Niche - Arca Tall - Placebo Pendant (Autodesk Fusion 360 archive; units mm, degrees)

design "Arca - Tall - Modular" references "Modular - Placedo - Cord Set", "Modular - Placebo - Bayonet Connector"
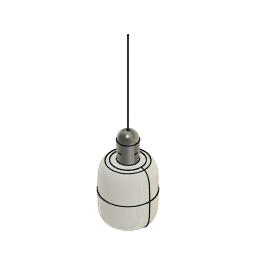
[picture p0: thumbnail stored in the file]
sketch "Sketch1" plane through (0, 0, 0) normal (0, 1, 0) x axis (1, 0, 0)
  line L1 (127, 0) -> (-127, 0)
  line L2 (0, 127) -> (0, -132.08)
  line L3 (26.9875, 127) -> (26.9875, -132.08)
  line L4 (-26.9875, 127) -> (-26.9875, -132.08)
  line L5 (127, -114.3) -> (-127, -114.3)
  line L6 (127, 114.3) -> (-127, 114.3)
  line L7 (95.25, 127) -> (95.25, -127)
  line L8 (-95.25, 127) -> (-95.25, -127)
  line L9 (127, -119.38) -> (-127, -119.38)
  line L10 (127, -132.08) -> (-127, -132.08)
  point P5 (26.9875, 127)
  point P6 (-26.9875, 127)
  point P7 (-127, -114.3)
  point P9 (-127, 114.3)
  point P8 (127, -114.3)
  point P10 (127, 114.3)
  point P12 (95.25, 127)
  point P14 (-95.25, 127)
  point P19 (-26.9875, -132.08)
  point P20 (0, -132.08)
  point P21 (26.9875, -132.08)
  horizontal L1
  vertical L2
  symmetric L2 P5 P6
  symmetric L1 P7 P9
  symmetric L1 P8 P10
  symmetric L2 P12 P14
  coincident L10 P19
  coincident L10 P20
  coincident L10 P21
  dimension "d2" = 114.3
  dimension "d3" = 95.25
  dimension "d4" = 119.38
  dimension "d5" = 132.08
derived_base_feature "Derived Base Feature"
sketch "Sketch2" plane through (0, 0, 0) normal (0, 1, 0) x axis (1, 0, 0)
  curve K1 (71.6837, -115.2107) -> (95.6809, -6.8986)
  curve K2 (52.8501, 110.047) -> (95.6809, -6.8478)
  line L1 (6.35, 114.3) -> (14.1394, 114.3)
  line L2 (0, 114.3) -> (6.35, 114.3)
  line L3 (95.6809, -6.8986) -> (95.6809, -6.8732)
  line L4 (95.6809, -6.8478) -> (95.6809, -6.8732)
  line L5 (0, 114.3) -> (0, -152.4)
  line L6 (26.9875, 114.3) -> (26.9875, -152.4)
  line L7 (127, 0) -> (-127, 0)
  line L8 (26.9875, -152.4) -> (26.9875, -124.1529)
  curve K3 (71.6837, -115.2107) -> (57.3444, -118.8227)
  curve K4 (97.0837, -115.2107) -> (121.0809, -6.8986)
  line L9 (-5.08, -132.08) -> (30.48, -132.08)
  curve K5 (95.6814, 4.9187) -> (95.6809, -6.8478)
  curve K6 (95.1681, 22.0412) -> (95.6814, 4.9187)
  curve K7 (94.696, 36.0588) -> (95.1681, 22.0412)
  curve K8 (94.3798, 46.8578) -> (94.696, 36.0588)
  curve K9 (93.5014, 59.02) -> (94.3798, 46.8578)
  curve K10 (92.6826, 66.7361) -> (93.5014, 59.02)
  curve K11 (87.4432, 83.6792) -> (92.6826, 66.7361)
  curve K12 (83.6663, 89.9171) -> (87.4432, 83.6792)
  curve K13 (81.2455, 93.6814) -> (83.6663, 89.9171)
  curve K14 (79.8608, 95.2739) -> (81.2455, 93.6814)
  curve K15 (76.5846, 98.3024) -> (79.8608, 95.2739)
  curve K16 (71.12, 103.378) -> (76.5846, 98.3024)
  curve K17 (62.23, 107.188) -> (71.12, 103.378)
  curve K18 (60.3553, 107.865) -> (62.23, 107.188)
  curve K19 (55.4987, 109.407) -> (60.3553, 107.865)
  curve K20 (54.6982, 109.6954) -> (55.4987, 109.407)
  curve K21 (52.8501, 110.047) -> (54.6982, 109.6954)
  curve K22 (95.6814, -18.6651) -> (95.6809, -6.8986)
  curve K23 (95.1681, -35.7876) -> (95.6814, -18.6651)
  curve K24 (94.696, -49.8052) -> (95.1681, -35.7876)
  curve K25 (94.3798, -60.6043) -> (94.696, -49.8052)
  curve K26 (93.5014, -72.7665) -> (94.3798, -60.6043)
  curve K27 (92.6826, -80.4825) -> (93.5014, -72.7665)
  curve K28 (87.4432, -97.4257) -> (92.6826, -80.4825)
  curve K29 (83.6663, -103.6635) -> (87.4432, -97.4257)
  curve K30 (81.2455, -107.4278) -> (83.6663, -103.6635)
  curve K31 (79.8608, -109.0204) -> (81.2455, -107.4278)
  curve K32 (77.083, -111.5881) -> (79.8608, -109.0204)
  curve K33 (75.5537, -112.9298) -> (77.083, -111.5881)
  curve K34 (71.6837, -115.2107) -> (75.5537, -112.9298)
  arc A1 centre (13.3279, -71.3849) radius 185.6867 clockwise from (14.1394, 114.3) to (52.8501, 110.047)
  arc A2 centre (29.1167, 64.7059) radius 185.6867 clockwise from (57.3444, -118.8227) to (30.1449, -120.978)
  arc A3 centre (30.1625, -124.1529) radius 3.175 clockwise from (26.9875, -124.1529) to (30.1449, -120.978)
  point P9 (0, 114.3)
  point P13 (0, 114.3)
  coincident P9 P13
  perpendicular L2 L5
  tangent A2 A3
  tangent L8 A3
  perpendicular L5 L9
  dimension "d6" = 26.9875
  dimension "d8" radius A3 = 3.175
revolve "Revolve1" sketch "Sketch2" AlongAngle 360 bodies "Arca Tall - Modular"
shell "Shell1" innerThickness 1.27
component_from_bodies "Body->Comp1"
component_insert "Component Insert1"
component_insert "Component Insert2"
sketch "Sketch3" plane through (0, 0, 0) normal (0, 1, 0) x axis (1, 0, 0)
  curve K1 (58.1849, -116.188) -> (46.5459, -119.1199)
  curve K2 (47.1736, -119.0144) -> (46.5459, -119.1199)
  curve K3 (49.4816, -118.6521) -> (47.1736, -119.0144)
  curve K4 (51.9142, -118.2661) -> (49.4816, -118.6521)
  curve K5 (54.2138, -117.7227) -> (51.9142, -118.2661)
  curve K6 (56.724, -116.9155) -> (54.2138, -117.7227)
  curve K7 (58.1849, -116.188) -> (56.724, -116.9155)
  curve K8 (58.1849, -116.188) -> (77.6633, -28.2722)
  curve K9 (77.6636, -37.823) -> (77.6633, -28.2722)
  curve K10 (77.247, -51.7211) -> (77.6636, -37.823)
  curve K11 (76.8638, -63.0991) -> (77.247, -51.7211)
  curve K12 (76.6071, -71.8645) -> (76.8638, -63.0991)
  curve K13 (75.8941, -81.7365) -> (76.6071, -71.8645)
  curve K14 (75.2295, -87.9995) -> (75.8941, -81.7365)
  curve K15 (70.9767, -101.7521) -> (75.2295, -87.9995)
  curve K16 (67.9111, -106.8153) -> (70.9767, -101.7521)
  curve K17 (65.9461, -109.8707) -> (67.9111, -106.8153)
  curve K18 (64.8222, -111.1634) -> (65.9461, -109.8707)
  curve K19 (62.5675, -113.2476) -> (64.8222, -111.1634)
  curve K20 (61.3262, -114.3366) -> (62.5675, -113.2476)
  curve K21 (58.1849, -116.188) -> (61.3262, -114.3366)
  curve K22 (42.8979, 66.6514) -> (77.6633, -28.2309)
  curve K23 (77.6636, -18.6802) -> (77.6633, -28.2309)
  curve K24 (77.247, -4.782) -> (77.6636, -18.6802)
  curve K25 (76.8638, 6.5959) -> (77.247, -4.782)
  curve K26 (76.6071, 15.3614) -> (76.8638, 6.5959)
  curve K27 (75.8941, 25.2333) -> (76.6071, 15.3614)
  curve K28 (75.2295, 31.4964) -> (75.8941, 25.2333)
  curve K29 (70.9767, 45.249) -> (75.2295, 31.4964)
  curve K30 (67.9111, 50.3122) -> (70.9767, 45.249)
  curve K31 (65.9461, 53.3676) -> (67.9111, 50.3122)
  curve K32 (64.8222, 54.6603) -> (65.9461, 53.3676)
  curve K33 (62.163, 57.1184) -> (64.8222, 54.6603)
  curve K34 (57.7274, 61.2383) -> (62.163, 57.1184)
  curve K35 (50.5115, 64.3308) -> (57.7274, 61.2383)
  curve K36 (48.9898, 64.8803) -> (50.5115, 64.3308)
  curve K37 (45.0478, 66.1319) -> (48.9898, 64.8803)
  curve K38 (44.398, 66.366) -> (45.0478, 66.1319)
  curve K39 (42.8979, 66.6514) -> (44.398, 66.366)
  line L1 (77.6633, -28.2722) -> (77.6633, -28.2516)
  line L2 (77.6633, -28.2309) -> (77.6633, -28.2516)
  line L3 (5.1542, 70.1035) -> (11.4768, 70.1035)
  line L4 (0, 70.1035) -> (5.1542, 70.1035)
  line L5 (0, -120.4006) -> (0, 70.1035)
  line L6 (0, 70.0994) -> (0, -120.4006)
  line L7 (0, -133.1006) -> (26.924, -133.1006)
  line L8 (0, -120.4006) -> (0, -133.1006)
  line L9 (26.924, -120.8356) -> (26.924, -133.1006)
  line L10 (26.924, 70.0994) -> (26.924, 69.242)
  arc A1 centre (23.6338, 29.8485) radius 150.72 clockwise from (46.5459, -119.1199) to (26.924, -120.8356)
  arc A2 centre (10.8181, -80.6151) radius 150.72 clockwise from (11.4768, 70.1035) to (42.8979, 66.6514)
  point P52 (26.924, 69.242)
  point P46 (0, -120.4006)
  point P47 (0, 70.0994)
  point P48 (26.924, -133.1006)
  point P49 (26.924, 70.0994)
  perpendicular L7 L9
  perpendicular L7 L8
  coincident A2 P52
  collinear L9 L10
  dimension "d11" distance P46 P47 = 190.5
  dimension "d13" distance P48 P49 = 203.2
revolve "Revolve2" sketch "Sketch3" AlongAngle 360 bodies "Arca Tall V2 - Modular"
shell "Shell2" innerThickness 1.27
component_from_bodies "Body->Comp2"
position "Position1"
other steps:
base_feature "Base Feature1" bodies "Arca Tall V2 - Modular"
base_feature "Base Feature1" bodies "Arca Tall - Modular"
create_component "CreateComponent1"
remove_body "RemoveBody1"
create_component "CreateComponent2"
remove_body "RemoveBody2"
named bodies: "Arca Tall - Modular", "Arca Tall V2 - Modular"

design "Modular - Placebo - Bayonet Connector"
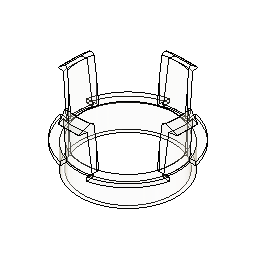
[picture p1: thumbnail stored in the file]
sketch "Sketch1" plane through (0, 0, 0) normal (0, 0, 1) x axis (1, 0, 0)
  circle C1 centre (0, 0) radius 23.241
  point P1 (0, 0)
  point P2 (0, 0)
  coincident P1 P2
  dimension "d1" diameter C1 = 46.482
extrude "Extrude1" new body sketch "Sketch1" along normal blind 11.176
sketch "Sketch2" plane through (0, 0, 11.176) normal (0, 0, 1) x axis (-1, 0, 0)
  line L1 (-23.2795, -6.35) -> (-26.1645, -6.35)
  line L2 (-23.2795, 6.35) -> (-26.1645, 6.35)
  line L3 (26.1645, -6.35) -> (23.2795, -6.35)
  line L4 (26.1645, 6.35) -> (23.2795, 6.35)
  line L5 (6.35, -23.2795) -> (6.35, -26.1645)
  line L6 (-6.35, -23.2795) -> (-6.35, -26.1645)
  line L7 (6.35, 26.1645) -> (6.35, 23.2795)
  line L8 (-6.35, 26.1645) -> (-6.35, 23.2795)
  line L9 (0, -24.13) -> (0, -26.924)
  line L10 (6.35, -23.2795) -> (6.35, -22.3567)
  line L11 (-6.35, -23.2795) -> (-6.35, -22.3567)
  line L12 (23.2795, -6.35) -> (22.3567, -6.35)
  line L13 (23.2795, 6.35) -> (22.3567, 6.35)
  line L14 (-23.2795, 6.35) -> (-22.3567, 6.35)
  line L15 (-23.2795, -6.35) -> (-22.3567, -6.35)
  line L16 (6.35, 22.3567) -> (6.35, 23.2795)
  line L17 (-6.35, 22.3567) -> (-6.35, 23.2795)
  circle C1 centre (0, 0) radius 23.241
  arc A1 centre (0, 0) radius 26.924 clockwise from (-6.35, -26.1645) to (-26.1645, -6.35)
  arc A2 centre (0, 0) radius 26.924 clockwise from (26.1645, -6.35) to (6.35, -26.1645)
  arc A3 centre (0, 0) radius 24.13 clockwise from (23.2795, 6.35) to (23.2795, -6.35)
  arc A4 centre (0, 0) radius 24.13 clockwise from (6.35, -23.2795) to (-6.35, -23.2795)
  arc A5 centre (0, 0) radius 26.924 clockwise from (6.35, 26.1645) to (26.1645, 6.35)
  arc A6 centre (0, 0) radius 26.924 clockwise from (-26.1645, 6.35) to (-6.35, 26.1645)
  arc A7 centre (0, 0) radius 24.13 clockwise from (-6.35, 23.2795) to (6.35, 23.2795)
  arc A8 centre (0, 0) radius 24.13 clockwise from (-23.2795, -6.35) to (-23.2795, 6.35)
  point P2 (0, 0)
  point P4 (0, 0)
  point P12 (-23.2795, -6.35)
  point P13 (-22.3567, -6.35)
  point P14 (-23.2795, 6.35)
  point P15 (-22.3567, 6.35)
  point P16 (22.3567, -6.35)
  point P18 (22.3567, 6.35)
  point P24 (6.35, 23.2795)
  point P28 (6.35, -22.3567)
  point P29 (-6.35, -22.3567)
  point P31 (-6.35, 26.1645)
  point P35 (0, -24.13)
  point P36 (6.35, 22.3567)
  point P37 (-6.35, 22.3567)
  coincident P2 P4
  vertical L9
  concentric A2 A3
  concentric A1 A2
  coincident P12 A3
  coincident C1 P13
  coincident P14 A3
  coincident C1 P15
  coincident C1 P16
  coincident C1 P18
  concentric A2 A5
  coincident P24 L5
  concentric A3 A7
  concentric A4 A7
  coincident C1 P28
  coincident C1 P29
  coincident P31 A5
  concentric A5 A6
  concentric A7 A8
  coincident A4 P35
  horizontal L12
  coincident C1 P36
  parallel L7 L16
  coincident C1 P37
  parallel L8 L17
  dimension "d4" diameter A2 = 53.848
extrude "Extrude2" add sketch "Sketch2" profile of C1 A8 L10 L11 L12 L13 L14 L15 L16 L17 along normal blind 0.762
extrude "Extrude3" add sketch "Sketch2" profile of C1 A6 L7 L8 L4 L3 L10 L11 L12 L13 L14 L15 L16 L17 along normal blind 1.7018
extrude "Extrude4" add sketch "Sketch2" profile of C1 along normal blind 1.7018
work_plane "WorkPlane1" AlongDistance 33.8963
sketch "Sketch3" plane through (0, 0, 33.8963) normal (0, 0, 1) x axis (1, 0, 0)
  line L1 (0, 20.3925) -> (0, 27.5045)
  line L2 (-6.604, 20.3925) -> (-6.604, 27.5045)
  line L3 (6.604, 20.3925) -> (6.604, 27.5045)
  circle C1 centre (0, 0) radius 23.7363
  circle C2 centre (0, 0) radius 27.305
  arc A1 centre (0.0021, 0.2001) radius 23.9364 clockwise from (-6.604, 23.2068) to (6.604, 23.208)
  arc A2 centre (0.0021, 0.2001) radius 21.3964 clockwise from (-6.604, 20.5511) to (6.604, 20.5525)
  point P1 (0, 0)
  point P2 (0, 0)
  point P6 (-6.604, 27.5045)
  point P8 (6.604, 27.5045)
  point P7 (-6.604, 20.3925)
  point P9 (6.604, 20.3925)
  point P11 (-6.604, 23.2068)
  point P12 (6.604, 23.208)
  point P14 (-6.604, 20.5511)
  point P15 (6.604, 20.5525)
  coincident P1 P2
  concentric C1 C2
  vertical L1
  symmetric L1 P6 P8
  symmetric L1 P7 P9
  tangent C1 A1
  coincident L2 P11
  coincident L3 P12
  concentric A1 A2
  coincident L2 P14
  coincident L3 P15
  dimension "d14" diameter C1 = 47.4726
  dimension "d15" diameter C2 = 54.61
  dimension "d16" = 6.604
extrude "Extrude5" new body sketch "Sketch3" profile of C1 L1 L2 L3 A1 A2 against normal blind 21.59
sketch "Sketch4" plane through (0, 0, 33.8963) normal (0, 0, 1) x axis (-1, 0, 0)
  line L1 (6.604, -20.5511) -> (6.604, -23.2068)
  line L2 (-6.604, -23.208) -> (-6.604, -20.5525)
  line L3 (-5.08, -26.67) -> (-6.604, -20.5525)
  line L4 (5.08, -26.67) -> (-5.08, -26.67)
  line L5 (6.604, -20.5511) -> (5.08, -26.67)
  arc A1 centre (-0.0021, -0.2001) radius 23.9364 clockwise from (6.604, -23.2068) to (-6.604, -23.208)
  arc A2 centre (-0.0021, -0.2001) radius 21.3964 clockwise from (6.604, -20.5511) to (-6.604, -20.5525)
  point P6 (-6.604, -20.5525)
  point P7 (-6.604, -20.5525)
  point P5 (6.604, -20.5511)
  point P10 (6.604, -20.5511)
  coincident P6 P7
  perpendicular L2 L4
  coincident P5 P10
extrude "Extrude6" add sketch "Sketch4" profile of A1 A2 L3 L4 L5 against normal blind 3.175
move "Move1"
sketch "Sketch5" plane through (0, 3.4565, 35.8974) normal (0, 0.0958, 0.9954) x axis (-1, 0, 0)
  line L1 (6.604, -19.277) -> (6.604, -21.9327)
  line L2 (-6.604, -21.9339) -> (-6.604, -19.2784)
  line L3 (-5.08, -25.3959) -> (-5.8947, -22.1257)
  line L4 (5.08, -25.3959) -> (-5.08, -25.3959)
  line L5 (5.8948, -22.1246) -> (5.08, -25.3959)
  line L6 (-8.1218, -17.3223) -> (-6.0831, -25.506)
  line L7 (-0.004, -17.3223) -> (-0.0002, -17.3223)
  line L8 (-8.1218, -17.3223) -> (-6.8295, -17.3223)
  line L9 (0, -25.3959) -> (0.0001, -20.3223)
  line L10 (-6.8295, -17.3223) -> (-4.7917, -25.5025)
  line L11 (8.1222, -17.3227) -> (6.0831, -25.5062)
  line L12 (8.1222, -17.3227) -> (6.8299, -17.3226)
  line L13 (-4.7917, -25.5025) -> (-6.1096, -25.506)
  line L14 (4.7917, -25.5027) -> (6.0831, -25.5062)
  line L15 (6.8299, -17.3226) -> (4.7917, -25.5027)
  arc A1 centre (-0.0021, 1.074) radius 23.9364 clockwise from (6.604, -21.9327) to (5.8948, -22.1246)
  arc A2 centre (-0.0021, 1.074) radius 21.3964 clockwise from (6.604, -19.277) to (-6.604, -19.2784)
  arc A3 centre (-0.0021, 1.074) radius 23.9364 clockwise from (-5.8947, -22.1257) to (-6.604, -21.9339)
  arc A4 centre (-0.0021, 1.074) radius 18.3964 clockwise from (5.6778, -16.4236) to (-5.6783, -16.4247)
  point P14 (-0.0002, -17.3223)
  point P15 (-8.1218, -17.3223)
  point P16 (-0.004, -17.3223)
  point P17 (0.0001, -20.3223)
  point P18 (0, -25.3959)
  point P20 (8.1222, -17.3227)
  point P19 (-6.8295, -17.3223)
  point P21 (6.8299, -17.3226)
  point P23 (-6.0831, -25.506)
  point P26 (6.8299, -17.3226)
  point P24 (-4.7917, -25.5025)
  point P25 (4.7917, -25.5027)
  midpoint A4 P14
  horizontal L7
  coincident P15 L7
  coincident A4 P16
  collinear L7 L8
  midpoint A2 P17
  midpoint L4 P18
  symmetric P15 L9 P20
  symmetric L9 P19 P21
  coincident L13 P23
  symmetric L9 P19 P26
  symmetric L9 P24 P25
  dimension "d22" = -3
extrude "Extrude7" cut sketch "Sketch5" profile of A1 L1 A2 L2 A3 L3 L4 L5 L8 L6 L10 L11 L12 L13 L14 L15 against normal blind 25.146 taper -1.45
remove_body "RemoveBody1"
remove_body "RemoveBody2"
chamfer "Chamfer1" sketch "Sketch4" distance 4.572 distance 3.048
circular_pattern "C-Pattern1" TotalAngle 360
extrude "Extrude8" add sketch "Sketch4" along a picked direction blind 0.508
extrude "Extrude9" add of existing geometry blind 0.508
extrude "Extrude10" add of existing geometry blind 0.508
extrude "Extrude11" add of existing geometry blind 0.508
hole "Hole1" sketch "Sketch4" HoleDepth 38.1 HoleDiameter 42.926 TipAngle 118
fillet "Fillet1" sketch "Sketch4" radius 1.27

design "Modular - Placedo - Cord Set"
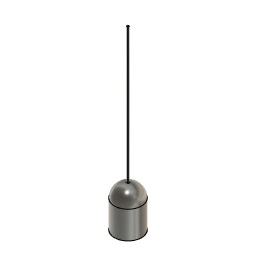
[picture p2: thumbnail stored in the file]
sketch "Sketch1" plane through (0, 0, 0) normal (0, 1, 0) x axis (1, 0, 0)
  line L1 (0, -88.9) -> (0, 0)
  line L2 (-29.5402, -88.9) -> (-29.5402, 0)
  line L3 (29.5402, -88.9) -> (29.5402, 0)
  line L4 (29.5402, 8.5598) -> (29.5402, -59.3598)
  line L5 (-29.5402, -59.3598) -> (-29.5402, 8.5598)
  line L6 (0, 38.1) -> (0, -88.9)
  line L7 (29.5402, 0) -> (-29.5402, 0)
  arc A1 centre (0, 8.5598) radius 29.5402 clockwise from (-29.5402, 8.5598) to (29.5402, 8.5598)
  arc A2 centre (0, -59.3598) radius 29.5402 clockwise from (29.5402, -59.3598) to (-29.5402, -59.3598)
  point P1 (0, 0)
  point P2 (0, 0)
  point P4 (-29.5402, 0)
  point P6 (29.5402, 0)
  point P5 (-29.5402, -88.9)
  point P7 (29.5402, -88.9)
  point P3 (0, -88.9)
  point P14 (0, 38.1)
  coincident P1 P2
  vertical L1
  symmetric L1 P4 P6
  symmetric L1 P5 P7
  tangent L4 A1
  tangent A1 L5
  parallel L4 L5
  tangent L5 A2
  tangent L4 A2
  midpoint P3 A2
  midpoint A1 P14
  parallel L1 L6
  dimension "d1" = 29.5402
revolve "Revolve1" sketch "Sketch1" AlongAngle 360
shell "Shell1" innerThickness 1.524
sketch "Sketch2" plane through (0, 0, 0) normal (0, 0, 1) x axis (1, 0, 0)
  circle C1 centre (0, 0) radius 2.8575
  point P1 (0, 0)
  point P2 (0, 0)
  coincident P1 P2
  dimension "d4" diameter C1 = 5.715
extrude "Extrude1" cut sketch "Sketch2" along normal blind 101.6
sketch "Sketch3" plane through (0, 0, 0) normal (0, 0, 1) x axis (1, 0, 0)
  circle C1 centre (0, 0) radius 2.286
  point P1 (0, 0)
  point P2 (0, 0)
  coincident P1 P2
  dimension "d7" diameter C1 = 4.572
extrude "Extrude2" new body sketch "Sketch3" along normal blind 304.8
move "Move1"
sketch "Sketch4" plane through (0, 0, 0) normal (0, 0, 1) x axis (1, 0, 0)
  circle C1 centre (0, 0) radius 18.796
  point P1 (0, 0)
  point P2 (0, 0)
  coincident P1 P2
  dimension "d10" diameter C1 = 37.592
extrude "Extrude3" new body sketch "Sketch4" along normal blind 31.75
move "Move2"
offset_faces "OffsetFaces1" distance 38.1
